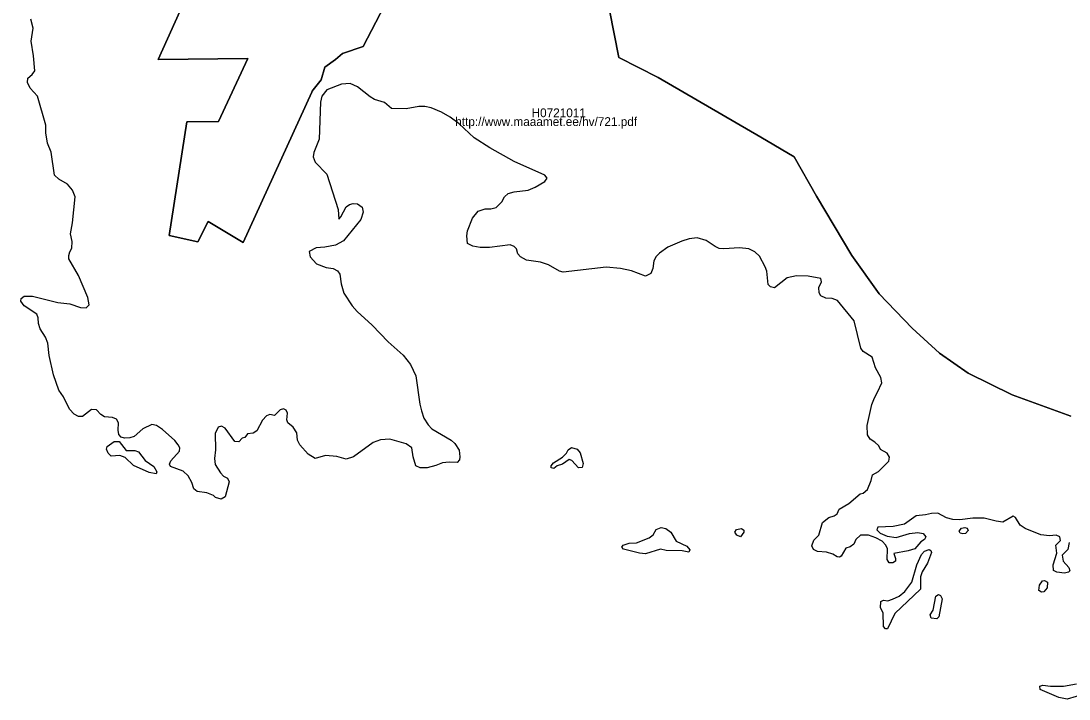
# Model space of a CAD drawing. Extents: x 369010 to 739155, y 6377141 to 6634081.
# Drawn here: x 385920 to 388897, y 6449332 to 6451258 of the extents above; entities that cross this region are included whole.
import ezdxf

# ---------------------------------------------------------------- set-up
doc = ezdxf.new("R2010")
doc.units = 0
for name, color, linetype in [('H_LINK', 7, 'Continuous'), ('H_PIIR', 7, 'Continuous'), ('H_TUNNUS', 7, 'Continuous')]:
    doc.layers.add(name, color=color, linetype=linetype)

msp = doc.modelspace()

# ---------------------------------------------------------------- linework, layer by layer
at = {"layer": 'H_PIIR'}
for points in [[(386471.79, 6451509.72), (386308.9201, 6451148.8799), (386564.15, 6451151.05), (386481.12, 6450972.4001), (386390.98, 6450971.6899), (386341.0699, 6450648.87), (386421.64, 6450630.1999), (386451.68, 6450687.8899), (386550.6701, 6450628.91), (386745.81, 6451055.7), (386747.2599, 6451058.8713), (386749.8704, 6451061.8952), (386772.3, 6451090.22), (386783.0999, 6451126.9399), (386813.33, 6451148.54), (386832.7601, 6451165.82), (386891.99, 6451185.7999), (387036.13, 6451462.54)], [(387036.13, 6451462.54), (386891.99, 6451185.7999), (386832.7601, 6451165.82), (386813.33, 6451148.54), (386783.0999, 6451126.9399), (386772.3, 6451090.22), (386749.8704, 6451061.8952), (386747.2599, 6451058.8713), (386745.81, 6451055.7), (386550.6701, 6450628.91), (386451.68, 6450687.8899), (386421.64, 6450630.1999), (386341.0699, 6450648.87), (386390.98, 6450971.6899), (386481.12, 6450972.4001), (386564.15, 6451151.05), (386308.9201, 6451148.8799), (386471.79, 6451509.72)], [(387591.73, 6451288.5801), (387617.9699, 6451153.66), (387730.35, 6451097.25), (388021.12, 6450927.58), (388116.18, 6450871.8599), (388179.62, 6450760.32), (388280.1, 6450591.71), (388357.7201, 6450483.0099), (388451.59, 6450385.0701), (388529.5899, 6450314.4), (388610.24, 6450257.3699), (388735.84, 6450195.38), (388901.94, 6450134.86)], [(388901.94, 6450134.86), (388735.84, 6450195.38), (388610.24, 6450257.3699), (388529.5899, 6450314.4), (388451.59, 6450385.0701), (388357.7201, 6450483.0099), (388280.1, 6450591.71), (388179.62, 6450760.32), (388116.18, 6450871.8599), (388021.12, 6450927.58), (387730.35, 6451097.25), (387617.9699, 6451153.66), (387591.73, 6451288.5801)], [(388897.95, 6449776.4847), (388893.6, 6449756.0646), (388878.0799, 6449740.2746), (388880.26, 6449723.1246), (388896.5899, 6449705.1646), (388899.0401, 6449696.1747), (388895.78, 6449691.8246), (388884.34, 6449688.8247), (388862.5699, 6449691.8246), (388853.3199, 6449696.7247), (388851.82, 6449712.5047), (388862.98, 6449745.9847), (388859.44, 6449769.1246), (388872.51, 6449782.4646), (388871.1499, 6449791.9947), (388860.2599, 6449797.1647), (388841.48, 6449795.5347), (388816.71, 6449798.2547), (388772.6201, 6449815.9546), (388758.46, 6449825.2046), (388745.13, 6449847.5347), (388738.5901, 6449851.3447), (388708.65, 6449833.9246), (388689.87, 6449836.9147), (388656.1201, 6449845.8946), (388623.46, 6449845.3446), (388586.99, 6449840.9947), (388567.1199, 6449842.0846), (388548.6099, 6449846.7146), (388524.66, 6449859.2346), (388506.7, 6449858.9647), (388489, 6449854.8847), (388463.14, 6449851.8946), (388429.67, 6449828.4847), (388397.5501, 6449821.6746), (388354, 6449819.5046), (388351.55, 6449812.6947), (388360.8, 6449802.6246), (388380.4, 6449794.4547), (388405.99, 6449790.3747), (388444.09, 6449802.0746), (388467.5, 6449804.8047), (388482.47, 6449802.3547), (388490.09, 6449792.2746), (388486.55, 6449784.9246), (388476.34, 6449778.6647), (388459.1899, 6449757.9747), (388439.87, 6449752.5346), (388399.04, 6449745.4546), (388404.4801, 6449730.4746), (388404.4801, 6449723.6746), (388396.3199, 6449719.0446), (388386.5199, 6449718.7747), (388380.2601, 6449728.0247), (388381.3499, 6449758.7946), (388376.99, 6449769.1346), (388366.3801, 6449779.7546), (388348.4099, 6449789.5546), (388327.7301, 6449797.1747), (388304.32, 6449797.1747), (388291.2599, 6449785.1947), (388285.5399, 6449771.8547), (388274.93, 6449763.9646), (388262.68, 6449760.4247), (388250.16, 6449737.8247), (388245.53, 6449734.2847), (388238.1799, 6449735.9246), (388226.2101, 6449742.7246), (388207.6899, 6449748.7247), (388182.9201, 6449750.6246), (388171.22, 6449756.6146), (388166.87, 6449766.6847), (388172.5801, 6449783.2947), (388185.92, 6449796.9046), (388196.53, 6449832.8446), (388214.77, 6449847.5447), (388230.01, 6449851.8946), (388238.1799, 6449857.3447), (388244.1601, 6449871.2246), (388271.6499, 6449886.7247), (388303.5001, 6449914.2247), (388312.7501, 6449916.3946), (388324.7299, 6449926.7446), (388335.07, 6449952.6046), (388338.88, 6449968.1247), (388355.4801, 6449978.4647), (388385.15, 6450007.5946), (388387.33, 6450019.0246), (388380.52, 6450029.9146), (388361.2001, 6450040.5346), (388356.5701, 6450050.8746), (388345.6901, 6450061.4947), (388332.3501, 6450069.6647), (388325, 6450082.4546), (388323.37, 6450108.8647), (388337.25, 6450168.4746), (388344.6, 6450187.2647), (388352.77, 6450203.8646), (388365.2901, 6450229.4547), (388362.8399, 6450245.5147), (388347.3299, 6450272.7447), (388337.8, 6450302.9546), (388311.94, 6450318.4746), (388305.6799, 6450328.5447), (388286.35, 6450405.5846), (388239.81, 6450463.8446), (388224.56, 6450469.5546), (388206.33, 6450470.3746), (388192.45, 6450476.6346), (388187.27, 6450485.6147), (388186.19, 6450500.8646), (388193.53, 6450517.1947), (388191.6301, 6450526.7246), (388156.52, 6450532.7146), (388122.49, 6450533.5247), (388096.63, 6450528.6346), (388060.71, 6450500.0547), (388049.27, 6450502.7747), (388042.7401, 6450509.0346), (388038.6601, 6450547.4247), (388034.3, 6450559.6746), (388017.7, 6450589.8947), (388004.91, 6450602.1447), (387987.49, 6450610.5846), (387961.08, 6450613.3046), (387916.45, 6450610.5846), (387903.1101, 6450611.9447), (387891.95, 6450617.1147), (387865.82, 6450634.0046), (387841.05, 6450641.6246), (387818.1899, 6450638.9046), (387796.69, 6450632.0947), (387757.6299, 6450614.9546), (387733.68, 6450598.6147), (387724.1599, 6450588.5446), (387717.62, 6450576.8447), (387714.3599, 6450554.5146), (387708.6401, 6450540.6346), (387693.94, 6450532.7446), (387654.4801, 6450547.7246), (387622.91, 6450554.8047), (387582.2199, 6450558.6146), (387460.29, 6450544.1746), (387449.67, 6450546.8946), (387418.64, 6450565.1347), (387395.51, 6450572.4846), (387355.5001, 6450578.2046), (387338.89, 6450587.4546), (387331.01, 6450596.1646), (387327.7399, 6450610.8647), (387320.66, 6450616.8546), (387309.78, 6450622.2947), (387250.9799, 6450614.4046), (387224.0401, 6450614.4046), (387203.0799, 6450617.9446), (387188.6499, 6450625.8347), (387186.21, 6450647.0647), (387187.84, 6450661.7646), (387202.81, 6450697.7046), (387218.05, 6450717.3046), (387238.19, 6450724.3847), (387254.5199, 6450724.1046), (387269.4899, 6450728.1946), (387286.1, 6450744.5247), (387293.1699, 6450758.4047), (387304.0599, 6450767.3946), (387320.66, 6450772.5746), (387360.1301, 6450777.4747), (387380, 6450785.6447), (387407.76, 6450801.9746), (387414.2999, 6450811.5047), (387408.0401, 6450819.9446), (387320.9401, 6450858.8647), (387251.8, 6450897.7946), (387207.3001, 6450926.1046), (387164.7, 6450965.3046), (387139.39, 6450984.3646), (387114.3501, 6450998.7946), (387085.23, 6451011.3147), (387066.72, 6451014.5847), (387049.57, 6451014.5747), (387013.64, 6451008.3147), (386972.54, 6451009.1346), (386952.4, 6451026.0146), (386923.8199, 6451034.9946), (386911.2901, 6451042.0546), (386875.3699, 6451070.3646), (386854.95, 6451080.4447), (386829.9101, 6451077.9947), (386788.8099, 6451062.2046), (386774.66, 6451043.9647), (386770.84, 6451027.3447), (386767.0301, 6450921.7247), (386751.25, 6450884.1547), (386750.1499, 6450871.6347), (386755.05, 6450857.2147), (386788.2599, 6450822.9146), (386820.92, 6450722.1947), (386822.55, 6450695.2446), (386828.8101, 6450701.7746), (386843.51, 6450730.0847), (386853.31, 6450736.3446), (386863.11, 6450739.3447), (386875.63, 6450738.5246), (386888.6899, 6450728.7246), (386892.2301, 6450714.5747), (386884.88, 6450693.8847), (386836.1599, 6450633.1747), (386813.57, 6450621.1947), (386782.81, 6450614.9347), (386758.04, 6450613.0347), (386738.7201, 6450603.2347), (386741.17, 6450587.9846), (386759.13, 6450567.8446), (386786.35, 6450557.7747), (386806.49, 6450554.5046), (386818.74, 6450548.2446), (386825.54, 6450538.9846), (386829.08, 6450510.6746), (386836.6999, 6450484.8146), (386860.9299, 6450448.6047), (386875.08, 6450432.2746), (386917.4, 6450393.8947), (386963.1299, 6450346.5247), (387005.8601, 6450308.6846), (387026.5399, 6450282.2946), (387040.9699, 6450249.6247), (387052.95, 6450169.3247), (387057.1699, 6450150.5346), (387064.2401, 6450129.3046), (387076.2199, 6450110.2446), (387087.1099, 6450099.3546), (387141.81, 6450067.2347), (387152.15, 6450057.1646), (387164.95, 6450038.6446), (387166.8501, 6450020.1346), (387165.22, 6450010.8846), (387158.6899, 6450003.2647), (387136.09, 6450004.8947), (387117.3101, 6450002.9846), (387098.2601, 6449995.0947), (387073.49, 6449988.2847), (387053.6299, 6449988.5646), (387041.6501, 6449994.2746), (387033.76, 6450020.1446), (387030.22, 6450045.7246), (387013.8899, 6450056.6146), (386967.34, 6450069.6847), (386940.6701, 6450067.7847), (386920.5301, 6450060.4347), (386863.9201, 6450020.1446), (386843.2301, 6450012.7946), (386816.83, 6450020.4147), (386784.9801, 6450023.6846), (386755.31, 6450014.9746), (386735.98, 6450027.4947), (386712.03, 6450053.3547), (386704.95, 6450066.6947), (386703.32, 6450087.6546), (386693.25, 6450104.2647), (386677.73, 6450116.2547), (386674.46, 6450124.4147), (386676.3699, 6450143.7446), (386673.37, 6450152.1847), (386665.21, 6450156.2746), (386655.95, 6450153.2747), (386639.9, 6450136.6746), (386626.8301, 6450140.2046), (386617.3, 6450136.3947), (386605.3299, 6450124.1446), (386590.09, 6450093.3846), (386578.9301, 6450087.1246), (386563.14, 6450085.2147), (386555.7899, 6450074.8747), (386547.6299, 6450072.9647), (386538.65, 6450062.3546), (386526.9399, 6450063.1747), (386499.7199, 6450101.5546), (386489.3799, 6450107.2746), (386480.1299, 6450103.7346), (386471.14, 6450086.3147), (386471.96, 6450039.4847), (386468.97, 6450015.2547), (386471.42, 6449998.1047), (386486.12, 6449974.4447), (386494.83, 6449965.1847), (386505.99, 6449959.1946), (386510.8901, 6449949.1246), (386500, 6449905.8346), (386488.3001, 6449899.0346), (386472.51, 6449903.9347), (386466.8, 6449909.9246), (386447.74, 6449917.8147), (386419.7101, 6449921.6246), (386410.4501, 6449928.4346), (386405.01, 6449946.4046), (386394.66, 6449965.7347), (386380.5101, 6449978.5247), (386344.5799, 6449992.4146), (386341.59, 6449998.3946), (386345.6699, 6450008.4747), (386370.44, 6450035.6946), (386370.7101, 6450044.9546), (386366.6301, 6450053.9347), (386356.8301, 6450066.1847), (386321.86, 6450097.7647), (386304.44, 6450108.9246), (386291.6501, 6450111.1047), (386265.5199, 6450099.3946), (386240.7499, 6450077.6147), (386229.3201, 6450073.2646), (386213.26, 6450072.4447), (386204.28, 6450075.9747), (386198.0199, 6450083.0546), (386195.57, 6450095.8546), (386196.9301, 6450115.9946), (386191.2201, 6450126.8846), (386180.06, 6450131.5146), (386156.6501, 6450133.1447), (386146.85, 6450139.6846), (386134.0601, 6450152.7447), (386119.6301, 6450154.1046), (386094.8701, 6450134.2347), (386083.1599, 6450134.5046), (386070.91, 6450140.4947), (386057.57, 6450155.4747), (386040.7, 6450190.3246), (386027.63, 6450209.1047), (386011.57, 6450252.9347), (385999.32, 6450307.1146), (385995.79, 6450342.7746), (385989.53, 6450359.9246), (385974.01, 6450383.6146), (385969.6601, 6450398.5846), (385968.29, 6450414.3646), (385964.21, 6450425.2546), (385929.0999, 6450448.9446), (385919.57, 6450461.7346), (385920.12, 6450469.3547), (385928.28, 6450475.8946), (385951.96, 6450476.4347), (386024.23, 6450458.1946), (386058.25, 6450454.3847), (386088.4701, 6450444.3146), (386104.8, 6450443.2246), (386112.96, 6450451.9246), (386109.1499, 6450472.6146), (386083.2901, 6450534.6847), (386055.8, 6450581.7846), (386055.5299, 6450591.3046), (386057.9801, 6450601.6547), (386064.5, 6450612.8246), (386065.3199, 6450631.6047), (386060.1499, 6450653.6546), (386066.14, 6450684.4246), (386073.76, 6450757.9247), (386065.59, 6450776.9747), (386051.9799, 6450793.8446), (386027.2199, 6450808.5447), (386014.7001, 6450819.9846), (386005.71, 6450885.3147), (385995.1, 6450910.6346), (385990.2, 6450939.7747), (385989.93, 6450961.8346), (385966.52, 6451044.3146), (385946.11, 6451067.4546), (385938.21, 6451083.2547), (385939.3, 6451094.9647), (385951.55, 6451106.1246), (385958.6301, 6451116.1947), (385955.36, 6451158.6646), (385948.8301, 6451200.5846), (385953.9999, 6451237.8847), (385948.01, 6451262.6547)], [(388943.3801, 6449346.0847), (388891.9399, 6449331.6547), (388868.53, 6449335.7447), (388814.91, 6449358.8746), (388813.82, 6449367.8647), (388822.8001, 6449371.4047), (388844.99, 6449368.4047), (388881.74, 6449367.8647), (388918.21, 6449374.9447)]]:
    msp.add_lwpolyline(points, dxfattribs=at)
for points in [[(386303.3884, 6449971.6839), (386283.5278, 6449974.994), (386239.1728, 6449995.1855), (386215.1748, 6450018.0251), (386200.9415, 6450023.1556), (386176.1158, 6450021.8315), (386167.675, 6450029.7757), (386162.5445, 6450041.1956), (386164.1995, 6450049.3052), (386184.06, 6450063.2076), (386198.9553, 6450063.2076), (386218.8158, 6450037.5544), (386243.3104, 6450037.8855), (386253.7372, 6450034.0789), (386272.2736, 6450009.7498), (386296.7682, 6449992.3719), (386305.2089, 6449976.649)], [(387503.4578, 6449988.8964), (387484.5905, 6450008.9223), (387477.4736, 6450012.3978), (387458.4407, 6449998.992), (387443.2144, 6449993.8614), (387433.2841, 6449986.5793), (387426.1674, 6449988.3998), (387426.1674, 6449994.1924), (387432.9531, 6450002.9641), (387458.4407, 6450019.0181), (387469.6951, 6450029.7757), (387474.6602, 6450040.037), (387483.2664, 6450046.1606), (387499.9823, 6450041.0301), (387508.5885, 6450031.0998), (387517.0292, 6450000.8126), (387513.719, 6449989.5582)], [(387797.8894, 6449752.7221), (387753.0378, 6449753.5496), (387736.8186, 6449757.6872), (387694.284, 6449744.6125), (387676.575, 6449745.9364), (387631.227, 6449757.5217), (387626.5929, 6449762.8179), (387630.0684, 6449768.7759), (387647.1154, 6449774.5687), (387668.1343, 6449775.5617), (387704.2142, 6449789.9605), (387715.634, 6449798.0701), (387724.2402, 6449813.2966), (387738.8045, 6449819.4201), (387751.7139, 6449816.2755), (387765.7816, 6449805.6834), (387780.8425, 6449780.0302), (387811.1298, 6449765.6314), (387820.067, 6449755.3701), (387817.0878, 6449749.081)], [(387964.0555, 6449792.6085), (387953.2977, 6449796.9117), (387948.1671, 6449805.8488), (387951.9737, 6449813.1311), (387966.8691, 6449815.7791), (387973.3237, 6449811.8071), (387972.8272, 6449805.5179)], [(388601.0803, 6449819.4201), (388607.3695, 6449817.1032), (388610.3486, 6449809.9866), (388603.0664, 6449802.3733), (388595.1222, 6449801.0492), (388588.0056, 6449803.2008), (388585.0265, 6449808.3314), (388591.3156, 6449817.1032)], [(388499.7919, 6449756.0322), (388504.4261, 6449753.3842), (388506.0811, 6449747.5914), (388495.3233, 6449717.4697), (388480.097, 6449693.4717), (388475.4628, 6449678.7418), (388474.9663, 6449643.324), (388402.1446, 6449574.8053), (388381.1255, 6449530.9467), (388375.3329, 6449530.9467), (388369.8713, 6449537.4015), (388369.0438, 6449576.4603), (388361.4305, 6449591.0248), (388362.258, 6449608.5681), (388369.8713, 6449612.5402), (388381.953, 6449610.7197), (388395.6899, 6449615.0228), (388414.5574, 6449623.7944), (388430.9422, 6449637.0348), (388450.1407, 6449663.5155), (388465.2016, 6449712.5047), (388477.7799, 6449741.9643), (388486.8825, 6449751.398)], [(388827.6553, 6449668.646), (388835.9305, 6449663.8464), (388834.6065, 6449647.4615), (388825.8349, 6449636.0418), (388818.5526, 6449635.7107), (388811.6015, 6449639.5173), (388813.0909, 6449655.5713), (388821.6971, 6449667.322)], [(388526.2725, 6449628.9252), (388532.2307, 6449625.6151), (388536.6994, 6449616.6778), (388527.4311, 6449565.537), (388521.3074, 6449559.2479), (388505.0881, 6449561.7304), (388503.102, 6449570.6677), (388511.0462, 6449584.57), (388519.1558, 6449623.7944)]]:
    msp.add_lwpolyline(points, close=True, dxfattribs=at)

# ---------------------------------------------------------------- texts
at = {"layer": 'H_LINK'}
msp.add_text('http://www.maaamet.ee/hv/721.pdf', height=25, dxfattribs=at).set_placement((387153.4247, 6450959.4941))
at = {"layer": 'H_TUNNUS'}
msp.add_text('H0721011', height=25, dxfattribs=at).set_placement((387370.2781, 6450984.4941))

doc.saveas('drawing.dxf')
